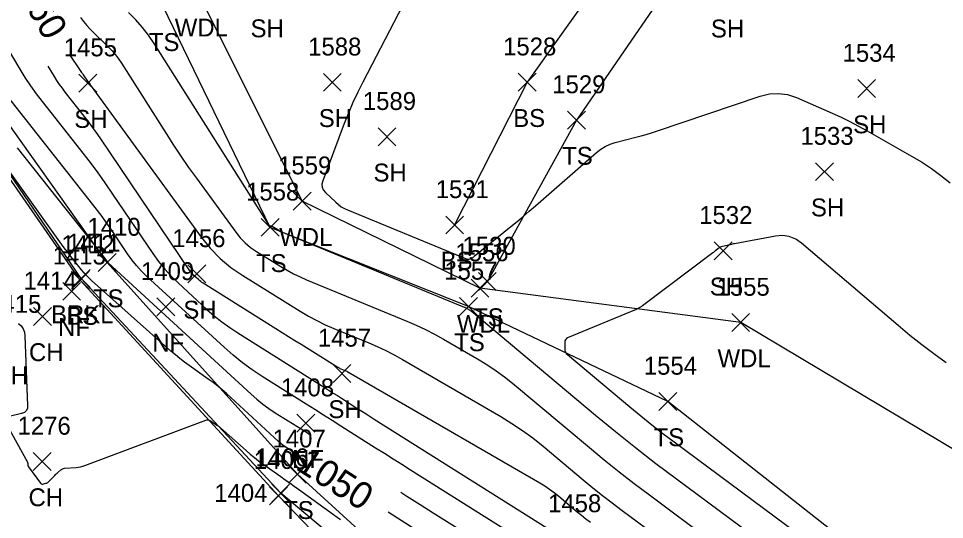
# Model space of a CAD drawing. Extents: x 1592612 to 1596497, y 111838 to 113741.
# Drawn here: x 1592923.4 to 1593027, y 113306.1 to 113362.1 of the extents above; entities that cross this region are included whole.
import ezdxf

# ---------------------------------------------------------------- set-up
doc = ezdxf.new("R2010")
doc.units = 0
for name, color, linetype in [('L_A', 7, 'Continuous'), ('L_I', 7, 'Continuous'), ('L_TIC', 7, 'Continuous'), ('LAWA', 7, 'Continuous'), ('LAWE', 7, 'Continuous'), ('LELB', 7, 'Continuous'), ('LSOGCMA', 7, 'Continuous'), ('LSOGCMA_T', 7, 'Continuous'), ('LSOGCMI', 7, 'Continuous')]:
    doc.layers.add(name, color=color, linetype=linetype)

msp = doc.modelspace()

# ---------------------------------------------------------------- linework, layer by layer
at = {"layer": 'L_TIC'}
for points in [[(1592930.16, 113353.86), (1592932.16, 113355.86)], [(1592932.16, 113353.86), (1592930.16, 113355.86)], [(1592957.51, 113353.95), (1592959.51, 113355.95)], [(1592959.51, 113353.95), (1592957.51, 113355.95)], [(1592979.31, 113353.96), (1592981.31, 113355.96)], [(1592981.31, 113353.96), (1592979.31, 113355.96)], [(1593017.29, 113353.25), (1593019.29, 113355.25)], [(1593019.29, 113353.25), (1593017.29, 113355.25)], [(1592984.82, 113349.73), (1592986.82, 113351.73)], [(1592986.82, 113349.73), (1592984.82, 113351.73)], [(1592963.63, 113347.86), (1592965.63, 113349.86)], [(1592965.63, 113347.86), (1592963.63, 113349.86)], [(1593012.57, 113343.96), (1593014.57, 113345.96)], [(1593014.57, 113343.96), (1593012.57, 113345.96)], [(1592954.15, 113340.66), (1592956.15, 113342.66)], [(1592956.15, 113340.66), (1592954.15, 113342.66)], [(1592950.57, 113337.73), (1592952.57, 113339.73)], [(1592952.57, 113337.73), (1592950.57, 113339.73)], [(1592971.2, 113338), (1592973.2, 113340)], [(1592973.2, 113338), (1592971.2, 113340)], [(1593001.25, 113335.11), (1593003.25, 113337.11)], [(1593003.25, 113335.11), (1593001.25, 113337.11)], [(1592932.33, 113333.79), (1592934.33, 113335.79)], [(1592934.33, 113333.79), (1592932.33, 113335.79)], [(1592942.36, 113332.52), (1592944.36, 113334.52)], [(1592944.36, 113332.52), (1592942.36, 113334.52)], [(1592929.32, 113331.83), (1592931.32, 113333.83)], [(1592931.32, 113331.83), (1592929.32, 113333.83)], [(1592929.41, 113332.01), (1592931.41, 113334.01)], [(1592931.41, 113332.01), (1592929.41, 113334.01)], [(1592974.86, 113331.67), (1592976.86, 113333.67)], [(1592976.86, 113331.67), (1592974.86, 113333.67)], [(1592928.35, 113330.58), (1592930.35, 113332.58)], [(1592930.35, 113330.58), (1592928.35, 113332.58)], [(1592974.03, 113330.94), (1592976.03, 113332.94)], [(1592976.03, 113330.94), (1592974.03, 113332.94)], [(1592938.89, 113328.83), (1592940.89, 113330.83)], [(1592940.89, 113328.83), (1592938.89, 113330.83)], [(1592972.74, 113328.88), (1592974.74, 113330.88)], [(1592974.74, 113328.88), (1592972.74, 113330.88)], [(1592925.09, 113327.77), (1592927.09, 113329.77)], [(1592927.09, 113327.77), (1592925.09, 113329.77)], [(1593003.2, 113327.08), (1593005.2, 113329.08)], [(1593005.2, 113327.08), (1593003.2, 113329.08)], [(1592958.59, 113321.39), (1592960.59, 113323.39)], [(1592960.59, 113321.39), (1592958.59, 113323.39)], [(1592995.05, 113318.25), (1592997.05, 113320.25)], [(1592997.05, 113318.25), (1592995.05, 113320.25)], [(1592954.54, 113315.83), (1592956.54, 113317.83)], [(1592956.54, 113315.83), (1592954.54, 113317.83)], [(1592925.05, 113311.54), (1592927.05, 113313.54)], [(1592927.05, 113311.54), (1592925.05, 113313.54)], [(1592953.6, 113310.11), (1592955.6, 113312.11)], [(1592955.6, 113310.11), (1592953.6, 113312.11)], [(1592951.5, 113307.71), (1592953.5, 113309.71)], [(1592953.5, 113307.71), (1592951.5, 113309.71)], [(1592951.74, 113308.01), (1592953.74, 113310.01)], [(1592953.74, 113308.01), (1592951.74, 113310.01)], [(1592951.74, 113308.01), (1592953.74, 113310.01)], [(1592953.74, 113308.01), (1592951.74, 113310.01)]]:
    msp.add_lwpolyline(points, dxfattribs=at)
at = {"layer": 'LAWA'}
msp.add_lwpolyline([(1593081.56, 113298.49), (1593031.2, 113311.98), (1593004.2, 113328.08), (1592975.03, 113331.94), (1592955.15, 113341.66), (1592943.47, 113365.08), (1592935.77, 113387.6), (1592932.92, 113413.66)], dxfattribs=at)
at = {"layer": 'LAWE'}
msp.add_lwpolyline([(1593001.92, 113269.88), (1592980.17, 113281.76), (1592972.08, 113292.77), (1592952.74, 113309.01), (1592930.41, 113333.01), (1592916.02, 113354.05), (1592913.1, 113363.09), (1592910.6, 113379.28), (1592906.83, 113388.64), (1592902.21, 113400.35), (1592897.68, 113413.91), (1592895.16, 113422.89), (1592891.07, 113425.25), (1592889.46, 113425.54), (1592888.74, 113438.02), (1592887.74, 113444.76), (1592887.5, 113453.35)], dxfattribs=at)
at = {"layer": 'LELB'}
for points in [[(1593000.61, 113268.02), (1592979.24, 113281.27), (1592969.82, 113290.67), (1592952.5, 113308.71), (1592930.32, 113332.83), (1592915.56, 113354.03), (1592906.59, 113378.23), (1592901.65, 113400.35), (1592897.34, 113413.71), (1592894.47, 113422.66), (1592891.54, 113424.97)], [(1593022.22, 113298.62), (1592996.05, 113319.25), (1592973.74, 113329.88), (1592951.57, 113338.73), (1592939.58, 113363.45), (1592930.76, 113371.37), (1592929.88, 113381.45), (1592924.73, 113386.6), (1592927.42, 113411.32), (1592932.96, 113414.13), (1592945.07, 113412.42), (1592963.6, 113404.82), (1592977.4, 113399.85), (1592996.45, 113393.06), (1593007.4, 113387.97)], [(1593038.15, 113384.28), (1593011.98, 113387.96), (1592995.33, 113376.06), (1592980.31, 113354.96), (1592972.2, 113339)], [(1593002.84, 113271.33), (1592982.23, 113284.25), (1592973.37, 113294.03), (1592954.6, 113311.11), (1592933.33, 113334.79), (1592919.47, 113354.27), (1592918.17, 113363.34), (1592916.48, 113374.12), (1592914.92, 113386.72)], [(1593157.22, 113351.76), (1593128.27, 113360.77), (1593100.02, 113367.91), (1593070.22, 113374.84), (1593038.27, 113383.44), (1593013.97, 113383.15), (1593000.04, 113371.42), (1592985.82, 113350.73), (1592975.86, 113332.67)]]:
    msp.add_lwpolyline(points, dxfattribs=at)
at = {"layer": 'LSOGCMA'}
for points in [[(1592929.07, 113358.1), (1592930.3, 113356.29), (1592930.38, 113356.16), (1592930.47, 113356.04), (1592930.55, 113355.92), (1592930.64, 113355.79), (1592931.13, 113355.09), (1592931.15, 113355.08), (1592931.16, 113355.06), (1592931.17, 113355.05), (1592931.18, 113355.04), (1592931.23, 113354.99), (1592931.24, 113354.97), (1592931.26, 113354.96), (1592931.27, 113354.95), (1592931.28, 113354.93), (1592931.42, 113354.7), (1592931.45, 113354.65), (1592931.48, 113354.61), (1592931.51, 113354.57), (1592931.54, 113354.53), (1592943.84, 113337.64), (1592944.84, 113336.39), (1592945.95, 113335.26), (1592947.17, 113334.24), (1592948.49, 113333.33), (1592954.93, 113329.34), (1592955.84, 113328.8), (1592956.77, 113328.3), (1592957.71, 113327.84), (1592958.68, 113327.42), (1592962.58, 113325.81), (1592963.54, 113325.39), (1592964.5, 113324.94), (1592965.43, 113324.46), (1592966.35, 113323.95), (1592977.38, 113317.56), (1592978.61, 113316.81), (1592979.8, 113316.02), (1592980.96, 113315.17), (1592982.09, 113314.27), (1592986.59, 113310.49), (1592987.66, 113309.61), (1592988.74, 113308.75), (1592989.83, 113307.9), (1592990.94, 113307.07), (1592995.38, 113303.77)], [(1592954.62, 113313.3), (1592953.59, 113313.95), (1592953.3, 113314.14), (1592953.01, 113314.34), (1592952.74, 113314.56), (1592952.48, 113314.79), (1592946.68, 113320.13), (1592946.19, 113320.56), (1592945.69, 113320.98), (1592945.17, 113321.38), (1592944.64, 113321.76), (1592942.51, 113323.27), (1592941.98, 113323.65), (1592941.46, 113324.05), (1592940.96, 113324.46), (1592940.46, 113324.89), (1592931.57, 113332.8), (1592931.27, 113333.08), (1592930.98, 113333.37), (1592930.71, 113333.68), (1592930.44, 113333.99), (1592929.42, 113335.28), (1592929.16, 113335.61), (1592928.91, 113335.94), (1592928.67, 113336.27), (1592928.42, 113336.6), (1592919.05, 113349.62)], [(1592969.75, 113303.68), (1592964.75, 113306.86)]]:
    msp.add_lwpolyline(points, dxfattribs=at)
at = {"layer": 'LSOGCMI'}
for points in [[(1592967.9, 113366.5), (1592961.93, 113354.98), (1592961.36, 113353.84), (1592960.82, 113352.69), (1592960.32, 113351.52), (1592959.85, 113350.33), (1592957.44, 113343.93), (1592957.35, 113343.57), (1592957.37, 113343.23), (1592957.5, 113342.92), (1592957.74, 113342.63), (1592958.9, 113341.53), (1592959.2, 113341.27), (1592959.52, 113341.04), (1592959.86, 113340.85), (1592960.22, 113340.68), (1592973.61, 113335.19), (1592973.68, 113335.17), (1592973.75, 113335.16), (1592973.82, 113335.17), (1592973.88, 113335.2), (1592974.15, 113335.33), (1592974.22, 113335.36), (1592974.28, 113335.4), (1592974.34, 113335.44), (1592974.4, 113335.49), (1592978.48, 113338.81), (1592979.18, 113339.39), (1592979.87, 113339.96), (1592980.55, 113340.55), (1592981.23, 113341.14), (1592988.08, 113347.12), (1592988.55, 113347.48), (1592989.05, 113347.79), (1592989.59, 113348.03), (1592990.15, 113348.21), (1592992.48, 113348.8), (1592993.06, 113348.96), (1592993.64, 113349.12), (1592994.21, 113349.3), (1592994.78, 113349.49), (1593006.39, 113353.41), (1593007.42, 113353.67), (1593008.44, 113353.72), (1593009.45, 113353.58), (1593010.45, 113353.24), (1593014.45, 113351.49), (1593015.44, 113351.04), (1593016.42, 113350.56), (1593017.38, 113350.06), (1593018.34, 113349.54), (1593023.31, 113346.71), (1593024.44, 113346.04), (1593025.54, 113345.32), (1593026.6, 113344.54), (1593027.62, 113343.72)], [(1592930.34, 113362.2), (1592930.68, 113361.74), (1592931.05, 113361.3), (1592931.43, 113360.88), (1592931.83, 113360.47), (1592933.48, 113358.87), (1592933.88, 113358.46), (1592934.26, 113358.03), (1592934.6, 113357.58), (1592934.92, 113357.1), (1592939.92, 113349.21), (1592940.74, 113347.94), (1592941.58, 113346.69), (1592942.44, 113345.44), (1592943.32, 113344.22), (1592947.71, 113338.19), (1592948.21, 113337.57), (1592948.76, 113337), (1592949.37, 113336.49), (1592950.03, 113336.04), (1592952.77, 113334.34), (1592953.47, 113333.93), (1592954.17, 113333.55), (1592954.9, 113333.2), (1592955.63, 113332.87), (1592966.86, 113328.24), (1592967.91, 113327.79), (1592968.95, 113327.3), (1592969.96, 113326.77), (1592970.96, 113326.22), (1592974.93, 113323.92), (1592975.9, 113323.33), (1592976.85, 113322.69), (1592977.77, 113322.02), (1592978.66, 113321.3), (1592987.28, 113314.09), (1592988.92, 113312.74), (1592990.59, 113311.4), (1592992.27, 113310.09), (1592993.98, 113308.81), (1593000.98, 113303.61)], [(1593008.86, 113301.76), (1592997.02, 113310.55), (1592994.72, 113312.29), (1592992.44, 113314.06), (1592990.19, 113315.86), (1592987.96, 113317.69), (1592974.05, 113329.34), (1592973.99, 113329.38), (1592973.94, 113329.43), (1592973.87, 113329.47), (1592973.81, 113329.5), (1592973.56, 113329.65), (1592973.5, 113329.69), (1592973.43, 113329.72), (1592973.37, 113329.75), (1592973.3, 113329.78), (1592952.88, 113338.21), (1592952.76, 113338.26), (1592952.64, 113338.32), (1592952.52, 113338.38), (1592952.41, 113338.45), (1592951.77, 113338.83), (1592951.75, 113338.85), (1592951.72, 113338.85), (1592951.7, 113338.86), (1592951.67, 113338.86), (1592951.56, 113338.85), (1592951.54, 113338.85), (1592951.52, 113338.86), (1592951.5, 113338.88), (1592951.48, 113338.9), (1592938.57, 113359.28), (1592937.94, 113360.21), (1592937.26, 113361.1), (1592936.52, 113361.95), (1592935.73, 113362.76)], [(1592920.45, 113361.55), (1592923.55, 113356.41), (1592924.13, 113355.48), (1592924.74, 113354.57), (1592925.38, 113353.68), (1592926.04, 113352.81), (1592930.34, 113347.37), (1592931.28, 113346.16), (1592932.19, 113344.94), (1592933.07, 113343.71), (1592933.94, 113342.45), (1592938.44, 113335.8), (1592939.07, 113334.91), (1592939.76, 113334.07), (1592940.49, 113333.27), (1592941.27, 113332.51), (1592944.48, 113329.56), (1592945.3, 113328.84), (1592946.15, 113328.16), (1592947.03, 113327.52), (1592947.94, 113326.92), (1592957.7, 113320.78), (1592958.16, 113320.49), (1592958.62, 113320.2), (1592959.08, 113319.91), (1592959.54, 113319.62), (1592961.37, 113318.45), (1592961.83, 113318.16), (1592962.29, 113317.87), (1592962.75, 113317.58), (1592963.21, 113317.29), (1592984.84, 113303.67)], [(1592987.39, 113305.71), (1592986.89, 113306.1), (1592986.4, 113306.49), (1592985.91, 113306.89), (1592983.85, 113308.62), (1592983.34, 113309.03), (1592982.81, 113309.41), (1592982.27, 113309.78), (1592981.71, 113310.12), (1592960.25, 113322.55), (1592960.16, 113322.6), (1592960.07, 113322.64), (1592959.98, 113322.69), (1592959.88, 113322.73), (1592959.5, 113322.88), (1592959.41, 113322.92), (1592959.32, 113322.97), (1592959.23, 113323.02), (1592959.14, 113323.07), (1592955.04, 113325.61), (1592954.32, 113326.05), (1592953.61, 113326.5), (1592952.9, 113326.94), (1592952.19, 113327.39), (1592944.08, 113332.49), (1592943.93, 113332.58), (1592943.8, 113332.68), (1592943.66, 113332.79), (1592943.54, 113332.9), (1592943.03, 113333.36), (1592942.91, 113333.48), (1592942.8, 113333.61), (1592942.69, 113333.74), (1592942.59, 113333.87), (1592932.53, 113348.76), (1592932.1, 113349.38), (1592931.66, 113349.98), (1592931.22, 113350.58), (1592930.76, 113351.17), (1592928.64, 113353.85), (1592928.32, 113354.28), (1592928, 113354.72), (1592927.7, 113355.17), (1592927.42, 113355.62), (1592926.73, 113356.77)], [(1592981.72, 113302.47), (1592967.26, 113311.58), (1592966.28, 113312.19), (1592965.31, 113312.81), (1592964.34, 113313.42), (1592963.36, 113314.04), (1592959.48, 113316.51), (1592958.51, 113317.13), (1592957.53, 113317.74), (1592956.56, 113318.36), (1592955.59, 113318.97), (1592950.68, 113322.06), (1592949.55, 113322.8), (1592948.47, 113323.59), (1592947.42, 113324.43), (1592946.4, 113325.32), (1592937.78, 113333.25), (1592937.18, 113333.83), (1592936.61, 113334.45), (1592936.09, 113335.1), (1592935.6, 113335.78), (1592933.72, 113338.56), (1592933.24, 113339.25), (1592932.75, 113339.93), (1592932.25, 113340.61), (1592931.73, 113341.27), (1592922.16, 113353.4)], [(1592923.25, 113347.62), (1592932.27, 113336.26), (1592932.37, 113336.12), (1592932.48, 113335.99), (1592932.58, 113335.86), (1592932.69, 113335.73), (1592933.29, 113334.96), (1592933.3, 113334.95), (1592933.32, 113334.93), (1592933.33, 113334.91), (1592933.34, 113334.89), (1592933.39, 113334.82), (1592933.41, 113334.8), (1592933.42, 113334.78), (1592933.43, 113334.77), (1592933.45, 113334.75), (1592949.44, 113320.06), (1592950.08, 113319.5), (1592950.74, 113318.97), (1592951.42, 113318.47), (1592952.13, 113318), (1592955.01, 113316.19), (1592955.73, 113315.74), (1592956.04, 113315.54)], [(1593027.19, 113323.57), (1593025.81, 113324.57), (1593024.46, 113325.59), (1593023.13, 113326.65), (1593021.83, 113327.74), (1593011, 113336.97), (1593010.35, 113337.42), (1593009.64, 113337.71), (1593008.89, 113337.81), (1593008.1, 113337.75), (1593003.52, 113336.9), (1593003.35, 113336.87), (1593003.18, 113336.83), (1593003.01, 113336.79), (1593002.84, 113336.75), (1593002.01, 113336.54), (1593001.92, 113336.51), (1593001.83, 113336.47), (1593001.75, 113336.42), (1593001.68, 113336.37), (1593001.39, 113336.11), (1593001.31, 113336.05), (1593001.24, 113335.99), (1593001.16, 113335.93), (1593001.09, 113335.87), (1592993.21, 113329.96), (1592993.15, 113329.92), (1592993.1, 113329.88), (1592993.04, 113329.85), (1592992.98, 113329.81), (1592992.75, 113329.68), (1592992.7, 113329.65), (1592992.64, 113329.61), (1592992.58, 113329.59), (1592992.52, 113329.56), (1592984.84, 113326.36), (1592984.7, 113326.28), (1592984.59, 113326.16), (1592984.53, 113326.02), (1592984.51, 113325.85), (1592984.52, 113325.11), (1592984.54, 113324.94), (1592984.59, 113324.78), (1592984.68, 113324.63), (1592984.81, 113324.51), (1592991.8, 113318.66), (1592993.02, 113317.65), (1592994.25, 113316.66), (1592995.5, 113315.69), (1592996.76, 113314.74), (1593016.75, 113299.91)], [(1592923.4, 113327.99), (1592923.71, 113327.7), (1592923.93, 113327.37), (1592924.07, 113327), (1592924.13, 113326.58), (1592924.43, 113318.78), (1592924.4, 113318.46), (1592924.28, 113318.2), (1592924.07, 113318.02), (1592923.76, 113317.9), (1592922.36, 113317.58)], [(1592922.01, 113316.8), (1592924.4, 113312.47), (1592924.42, 113312.43), (1592924.43, 113312.39), (1592924.44, 113312.35), (1592924.44, 113312.3), (1592924.45, 113312.13), (1592924.46, 113312.08), (1592924.47, 113312.04), (1592924.49, 113312), (1592924.51, 113311.96), (1592925.87, 113310.12), (1592925.93, 113310.06), (1592925.99, 113310.03), (1592926.06, 113310.01), (1592926.14, 113310.02), (1592926.48, 113310.1), (1592926.56, 113310.12), (1592926.63, 113310.16), (1592926.7, 113310.21), (1592926.77, 113310.26), (1592927.47, 113310.99), (1592927.55, 113311.07), (1592927.63, 113311.15), (1592927.72, 113311.23), (1592927.8, 113311.31), (1592928.15, 113311.61), (1592928.24, 113311.68), (1592928.34, 113311.73), (1592928.44, 113311.76), (1592928.55, 113311.78), (1592929.84, 113311.88), (1592930.09, 113311.91), (1592930.34, 113311.95), (1592930.59, 113312.01), (1592930.83, 113312.09), (1592944.35, 113317.16), (1592944.49, 113317.2), (1592944.62, 113317.2), (1592944.75, 113317.17), (1592944.87, 113317.1), (1592945.58, 113316.6), (1592945.59, 113316.6), (1592945.61, 113316.59), (1592945.62, 113316.59), (1592945.63, 113316.58), (1592945.68, 113316.57), (1592945.69, 113316.57), (1592945.7, 113316.56), (1592945.71, 113316.56), (1592945.72, 113316.55), (1592948.86, 113313.76), (1592949.32, 113313.36), (1592949.79, 113312.98), (1592950.27, 113312.61), (1592950.77, 113312.25), (1592952.75, 113310.85), (1592953.25, 113310.5), (1592953.75, 113310.15), (1592954.24, 113309.79), (1592954.74, 113309.44), (1592958.64, 113306.61), (1592959.04, 113306.33), (1592959.44, 113306.04)], [(1592966.17, 113309.11), (1592966.85, 113308.67), (1592968.33, 113307.74), (1592969.81, 113306.8), (1592971.29, 113305.87), (1592978.6, 113301.27), (1592979.39, 113300.79), (1592980.18, 113300.32), (1592980.98, 113299.88), (1592981.8, 113299.45), (1592985.07, 113297.78), (1592985.88, 113297.34), (1592986.66, 113296.87), (1592987.42, 113296.36), (1592988.16, 113295.81), (1592996.47, 113289.3), (1592997.76, 113288.3), (1592999.04, 113287.29), (1593000.32, 113286.27), (1593001.6, 113285.26), (1593009.26, 113279.16)]]:
    msp.add_lwpolyline(points, dxfattribs=at)

# ---------------------------------------------------------------- texts
at = {"layer": 'L_A'}
for s, p in [('WDL', (1592940.89, 113360.08)), ('SH', (1592949.37, 113359.99)), ('SH', (1593000.87, 113359.97)), ('TS', (1592937.99, 113358.45)), ('SH', (1592929.65, 113349.86)), ('SH', (1592957, 113349.95)), ('BS', (1592978.75, 113349.96)), ('SH', (1593016.78, 113349.25)), ('TS', (1592984.23, 113345.73)), ('SH', (1592963.12, 113343.86)), ('SH', (1593012.06, 113339.96)), ('WDL', (1592952.57, 113336.66)), ('TS', (1592949.98, 113333.73)), ('BS', (1592970.64, 113334)), ('SH', (1593000.74, 113331.11)), ('TS', (1592931.74, 113329.79)), ('BRKL', (1592927.05, 113328.01)), ('SH', (1592941.85, 113328.52)), ('BS', (1592928.76, 113327.83)), ('WDL', (1592972.45, 113326.94)), ('TS', (1592974.27, 113327.67)), ('NF', (1592927.83, 113326.58)), ('TS', (1592972.15, 113324.88)), ('NF', (1592938.37, 113324.83)), ('CH', (1592924.58, 113323.77)), ('WDL', (1593001.61, 113323.08)), ('CH', (1592920.62, 113321.17)), ('SH', (1592958.08, 113317.39)), ('TS', (1592994.46, 113314.25)), ('NF', (1592954.02, 113311.83)), ('CH', (1592924.53, 113307.54)), ('TS', (1592953.01, 113306.11))]:
    msp.add_text(s, height=2, dxfattribs=at).set_placement(p)
at = {"layer": 'L_I'}
for s, p in [('1455', (1592928.47, 113357.86)), ('1588', (1592955.81, 113357.95)), ('1528', (1592977.62, 113357.96)), ('1534', (1593015.6, 113357.25)), ('1529', (1592983.12, 113353.73)), ('1589', (1592961.93, 113351.86)), ('1533', (1593010.88, 113347.96)), ('1559', (1592952.45, 113344.66)), ('1558', (1592948.87, 113341.73)), ('1531', (1592970.08, 113342)), ('1532', (1592999.56, 113339.11)), ('1410', (1592931.12, 113337.79)), ('1456', (1592940.61, 113336.52)), ('1412', (1592928.19, 113335.83)), ('1411', (1592928.85, 113336.01)), ('1530', (1592973.08, 113335.67)), ('1413', (1592927.23, 113334.58)), ('1556', (1592972.28, 113334.94)), ('1409', (1592937.11, 113332.83)), ('1557', (1592971.04, 113332.88)), ('1414', (1592923.97, 113331.77)), ('1555', (1593001.5, 113331.08)), ('1415', (1592920.01, 113329.17)), ('1457', (1592956.9, 113325.39)), ('1554', (1592993.36, 113322.25)), ('1408', (1592952.76, 113319.83)), ('1276', (1592923.3, 113315.54)), ('1407', (1592951.83, 113314.11)), ('1405', (1592949.73, 113311.71)), ('1406', (1592949.91, 113312.01)), ('1406', (1592949.91, 113312.01)), ('1404', (1592945.31, 113308.03)), ('1458', (1592982.65, 113306.87))]:
    msp.add_text(s, height=2, dxfattribs=at).set_placement(p)
at = {"layer": 'LSOGCMA_T'}
for s, rotation, p in [('1060', 299.7115, (1592922, 113367.23)), ('1050', 327.5785, (1592954.29, 113311.73))]:
    msp.add_text(s, height=3, rotation=rotation, dxfattribs=at).set_placement(p)

doc.saveas('drawing.dxf')
